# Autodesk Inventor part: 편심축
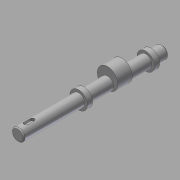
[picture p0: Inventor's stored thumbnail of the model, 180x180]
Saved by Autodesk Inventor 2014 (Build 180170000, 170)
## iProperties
Created: 2016-02
Part Number: 편심축
Material: 강철, 연강
Document SubType Name: Modeling
Designer: mduedu
Density: 1 g/cm^3
Appearance: 강철
Author: mduedu
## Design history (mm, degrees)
sketch "스케치1"
  geometry: C1 r 6 at (0, 0); 1 further point
  constraints: 1 centre point, 1 coincident
  dimensions: "d0" = 12 diameter of C1
extrude "돌출1" new body sketch "스케치1" distance "d1" = 140; taper "d2" = 0 deg
chamfer "모따기1" distance "d3" = 1; stored, may be unused: second distance "d4" = 2, angle "d5" = 45 deg
node "작업 평면1"
sketch "스케치2"
  geometry: C1 r 10 at (0, 4); C2 r 6 at (0, 0) reference; 1 further point
  constraints: 1 centre point, 1 tangent, 1 vertical alignment
  dimensions: "d7" = 20 diameter of C1
extrude "돌출2" join sketch "스케치2" stored distance "d8" = 14; taper "d9" = 0 deg
node "작업 평면2"
sketch "스케치3"
  geometry: C1 r 8.5 at (0, 0); 1 further point
  constraints: 1 centre point, 1 coincident
  dimensions: "d12" = 17 diameter of C1
extrude "돌출3" join sketch "스케치3" distance "d13" = 5; taper "d14" = 0 deg
node "작업 평면3"
sketch "스케치4"
  geometry: L1 (-5, 140)-(5, 140) reference; L2 (0, 140)-(0, 0); L3 (-2, 132)-(-2, 126); L4 (2, 126)-(2, 132); A1 r 2 centre (0, 132) between (2, 132) and (-2, 132); A2 r 2 centre (0, 126) between (-2, 126) and (2, 126)
  constraints: 6 end point, 4 point on circle, 4 tangent, 2 centre point, 2 point on line, 1 midpoint, 1 parallel, 1 perpendicular
  dimensions: "d15" = 4 distance between parallel lines of L3 L4; "d17" = 6 distance edge to line of A1 L1; "d18" = 10 dimension on A2 A1
extrude "돌출4" cut sketch "스케치4" distance "d19" = 2.5; taper "d20" = 0 deg
sketch "스케치5"
  geometry: L1 (6, 53)-(6, 139) reference; L2 (-6, 53)-(-6, 139) reference; L3 (6, 115)-(-6, 115); L4 (-5, 140)-(5, 140) reference; L5 (6, 116.5)-(4.5, 115); L6 (6, 116.5)-(6, 115); L7 (4.5, 115)-(6, 115); 1 further point
  constraints: 8 end point, 4 point on line, 2 collinear, 1 perpendicular
  dimensions: "d21" = 25 distance between parallel lines of L3 L4; "d22" = 3 diameter of L5.start L3; "d24" = 45 deg angle of L3 L5
revolve "회전1" sketch "스케치5" stored, may be unused: angle "d25" = 90 deg
sketch "스케치6"
  geometry: L1 (6, 116.5)-(4.5, 115) reference; L2 (6, 113.5)-(4.5, 115) reference; 2 further points
  constraints: 1 coincident
node "작업 평면4"
sketch "스케치7"
  geometry: C1 r 8.5 at (0, -4); 1 further point
  constraints: 1 centre point, 1 coincident
  dimensions: "d27" = 17 diameter of C1
extrude "돌출5" join sketch "스케치7" distance "d29" = 5; taper "d30" = 0 deg
node "솔리드1"
other parameters: "d6" = -46, "d11" = -11, "d26" = 28
